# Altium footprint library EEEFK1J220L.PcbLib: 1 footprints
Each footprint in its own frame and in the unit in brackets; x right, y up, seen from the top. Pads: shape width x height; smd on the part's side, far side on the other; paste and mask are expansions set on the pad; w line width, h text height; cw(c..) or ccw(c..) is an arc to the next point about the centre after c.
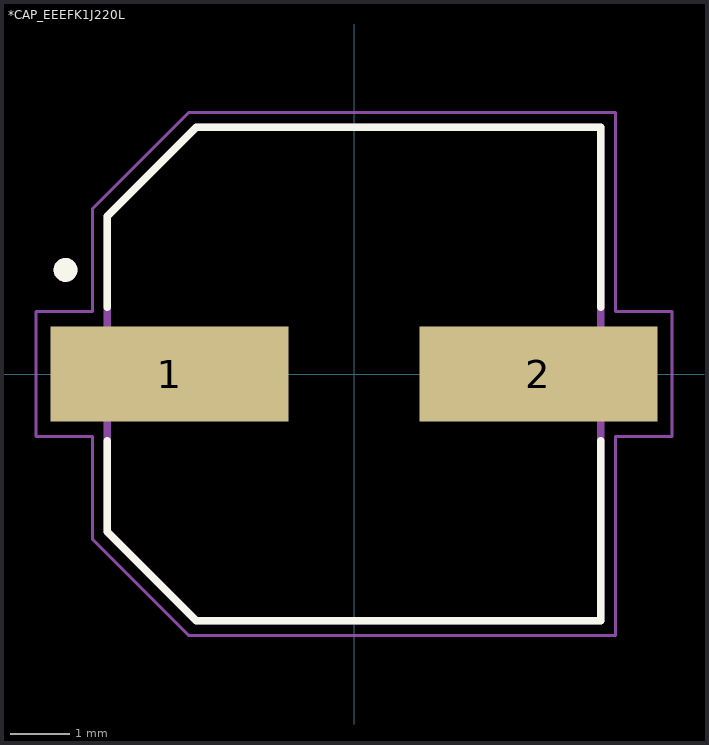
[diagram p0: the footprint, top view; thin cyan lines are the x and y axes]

## *CAP_EEEFK1J220L [mm]
pads (2):
  rect 4x1.6 smd: 1(-3.1,0) 2(3.1,0)
Top Overlay:
  circle w0.2: c-4.85,1.75 r0.1
  lines w0.127: -4.15,-1.12 -4.15,-2.65 -2.65,-4.15 4.15,-4.15 4.15,-1.12 ; -4.15,1.12 -4.15,2.65 -2.65,4.15 4.15,4.15 4.15,1.12
Mechanical 4:
  circle w0.2: c-4.85,1.75 r0.1
  circle w0.2: c-4.85,1.75 r0.1
  lines w0.127: -4.15,-2.65 -2.65,-4.15 ; -4.15,-2.65 -4.15,2.65 ; -4.15,-2.65 -2.65,-4.15 ; -4.15,-2.65 -4.15,2.65 ; -4.15,2.65 -2.65,4.15 ; -4.15,2.65 -2.65,4.15 ; -2.65,-4.15 4.15,-4.15 ; -2.65,-4.15 4.15,-4.15 ; -2.65,4.15 4.15,4.15 ; -2.65,4.15 4.15,4.15 ; 4.15,-4.15 4.15,4.15 ; 4.15,-4.15 4.15,4.15
Mechanical 16:
  lines w0.05: -5.35,-1.05 -5.35,1.05 -4.4,1.05 -4.4,2.775 -2.775,4.4 4.4,4.4 4.4,1.05 5.35,1.05 5.35,-1.05 4.4,-1.05 4.4,-4.4 -2.775,-4.4 -4.4,-2.775 -4.4,-1.05 -5.35,-1.05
